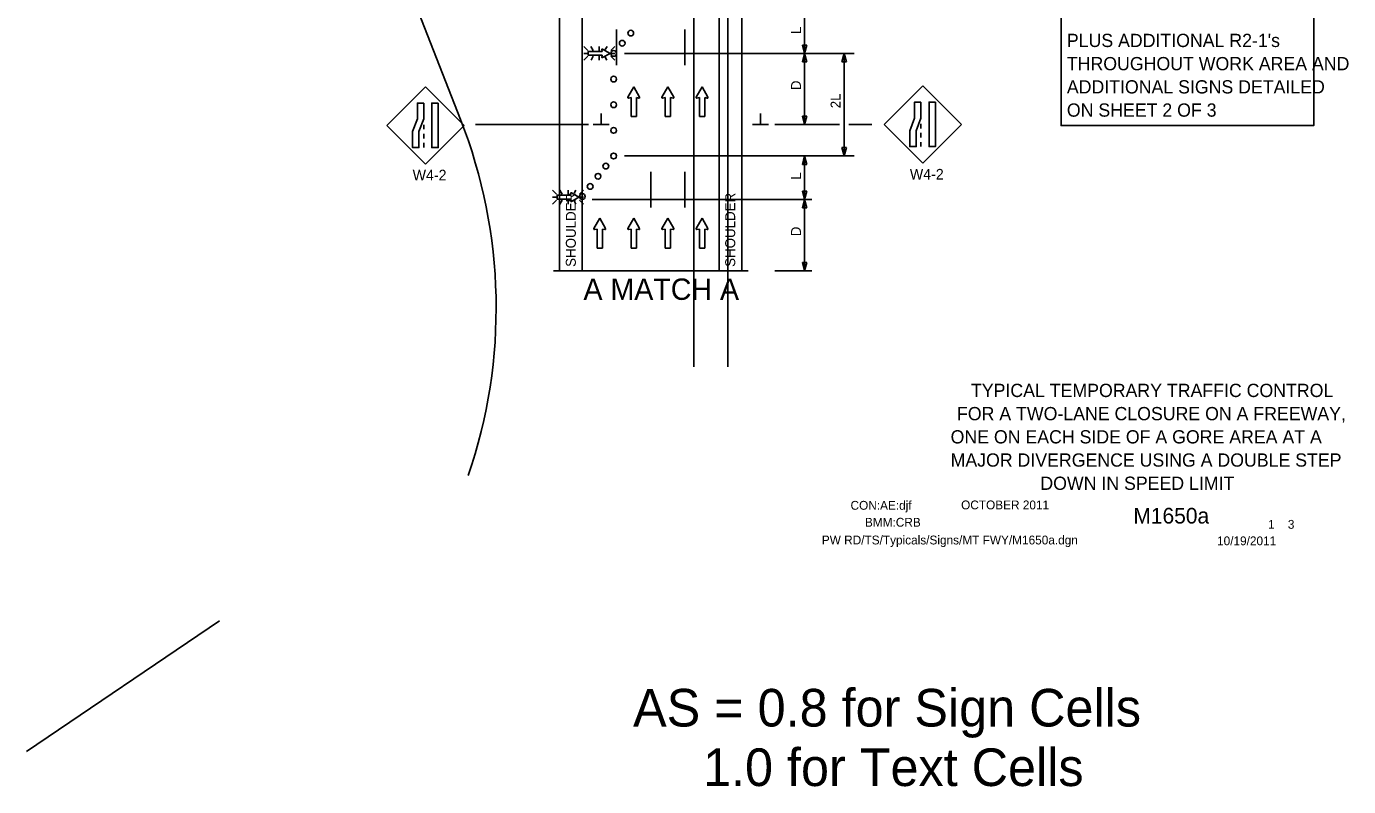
# Model space of a CAD drawing. Extents: x 16512 to 19509, y 5761 to 6974.
# Drawn here: x 16512 to 17440, y 5764 to 6297 of the extents above; entities that cross this region are included whole.
import ezdxf

# ---------------------------------------------------------------- set-up
doc = ezdxf.new("R2010")
doc.units = 0
for name, color, linetype in [('ALI_LEGAL_EX', 7, 'Continuous'), ('BORDER', 7, 'Continuous'), ('BORDER_SIGNAL_WO', 7, 'Continuous'), ('MT_SCRATCH_LEVEL_E', 7, 'Continuous'), ('PAVT_EDGE_EX', 7, 'Continuous'), ('TRAFFIC_SIGNS_PR', 7, 'Continuous'), ('TYPICAL_TEXT_DIMEN_EX', 7, 'Continuous'), ('TYPICAL_TEXT_DIMEN_PR', 7, 'Continuous')]:
    doc.layers.add(name, color=color, linetype=linetype)

msp = doc.modelspace()

# ---------------------------------------------------------------- linework, layer by layer
at = {"layer": 'ALI_LEGAL_EX'}
for p, q in [((16980.68, 6974.12), (16980.68, 6155.98)), ((17004.68, 6974.12), (17004.68, 6155.98)), ((16980.68, 6922.21), (16980.68, 6058.3)), ((17004.68, 6922.21), (17004.68, 6058.3)), ((16594.98, 6800.51), (16817, 6232.14))]:
    msp.add_line(p, q, dxfattribs=at)
for points in [[(16926.45, 6270.33), (16926.45, 6295.33)], [(16974.45, 6270.33), (16974.45, 6295.33)], [(16950.45, 6170.33), (16950.45, 6195.33)], [(16974.45, 6170.33), (16974.45, 6195.33)]]:
    msp.add_lwpolyline(points, dxfattribs=at)
msp.add_arc((16477.95, 6099.7), 364, 341.14594, 21.33672, dxfattribs=at)
at = {"layer": 'BORDER'}
msp.add_line((17289.25, 6011.25), (17289.25, 6011.25), dxfattribs=at)
msp.add_line((17289.25, 6011.25), (17289.25, 6011.25), dxfattribs=at)
at = {"layer": 'MT_SCRATCH_LEVEL_E'}
for p, q in [((16938.54, 6255.03), (16934.43, 6247.79)), ((16942.69, 6247.79), (16938.54, 6255.03)), ((16962.45, 6255.03), (16958.33, 6247.79)), ((16966.59, 6247.79), (16962.45, 6255.03)), ((16986.5, 6255.03), (16982.39, 6247.79)), ((16990.65, 6247.79), (16986.5, 6255.03)), ((16934.91, 6247.11), (16936.69, 6247.43)), ((16936.69, 6247.43), (16936.69, 6234.17)), ((16940.43, 6234.17), (16940.43, 6247.43)), ((16940.43, 6247.43), (16942.21, 6247.11)), ((16958.82, 6247.11), (16960.59, 6247.43)), ((16960.59, 6247.43), (16960.59, 6234.17)), ((16964.34, 6234.17), (16964.34, 6247.43)), ((16964.34, 6247.43), (16966.11, 6247.11)), ((16982.87, 6247.11), (16984.65, 6247.43)), ((16984.65, 6247.43), (16984.65, 6234.17)), ((16988.39, 6234.17), (16988.39, 6247.43)), ((16988.39, 6247.43), (16990.17, 6247.11)), ((16936.69, 6234.17), (16940.43, 6234.17)), ((16960.59, 6234.17), (16964.34, 6234.17)), ((16984.65, 6234.17), (16988.39, 6234.17)), ((16914.64, 6162.72), (16910.53, 6155.48)), ((16918.78, 6155.48), (16914.64, 6162.72)), ((16938.54, 6162.72), (16934.43, 6155.48)), ((16942.69, 6155.48), (16938.54, 6162.72)), ((16962.45, 6162.72), (16958.33, 6155.48)), ((16966.59, 6155.48), (16962.45, 6162.72)), ((16986.5, 6162.72), (16982.39, 6155.48)), ((16990.65, 6155.48), (16986.5, 6162.72)), ((16911.01, 6154.79), (16912.79, 6155.11)), ((16912.79, 6155.11), (16912.79, 6141.85)), ((16916.53, 6141.85), (16916.53, 6155.11)), ((16916.53, 6155.11), (16918.31, 6154.79)), ((16934.91, 6154.79), (16936.69, 6155.11)), ((16936.69, 6155.11), (16936.69, 6141.85)), ((16940.43, 6141.85), (16940.43, 6155.11)), ((16940.43, 6155.11), (16942.21, 6154.79)), ((16958.82, 6154.79), (16960.59, 6155.11)), ((16960.59, 6155.11), (16960.59, 6141.85)), ((16964.34, 6141.85), (16964.34, 6155.11)), ((16964.34, 6155.11), (16966.11, 6154.79)), ((16982.87, 6154.79), (16984.65, 6155.11)), ((16984.65, 6155.11), (16984.65, 6141.85)), ((16988.39, 6141.85), (16988.39, 6155.11)), ((16988.39, 6155.11), (16990.17, 6154.79)), ((16912.79, 6141.85), (16916.53, 6141.85)), ((16936.69, 6141.85), (16940.43, 6141.85)), ((16960.59, 6141.85), (16964.34, 6141.85)), ((16984.65, 6141.85), (16988.39, 6141.85))]:
    msp.add_line(p, q, dxfattribs=at)
for centre, start, end in [((16934.84, 6247.57), 150.42484, 279.96381), ((16942.28, 6247.57), 260.03619, 29.77312), ((16958.74, 6247.57), 150.42484, 279.96381), ((16966.18, 6247.57), 260.03619, 29.77312), ((16982.8, 6247.57), 150.42484, 279.96381), ((16990.24, 6247.57), 260.03619, 29.77312), ((16910.93, 6155.25), 150.42484, 279.96381), ((16918.38, 6155.25), 260.03619, 29.77312), ((16934.84, 6155.25), 150.42484, 279.96381), ((16942.28, 6155.25), 260.03619, 29.77312), ((16958.74, 6155.25), 150.42484, 279.96381), ((16966.18, 6155.25), 260.03619, 29.77312), ((16982.8, 6155.25), 150.42484, 279.96381), ((16990.24, 6155.25), 260.03619, 29.77312)]:
    msp.add_arc(centre, 0.463, start, end, dxfattribs=at)
at = {"layer": 'PAVT_EDGE_EX'}
for p, q in [((16886.45, 6480.53), (16886.45, 6125.9)), ((16902.45, 6480.53), (16902.45, 6125.9)), ((16998.45, 6480.53), (16998.45, 6125.9)), ((17014.45, 6480.53), (17014.45, 6125.9))]:
    msp.add_line(p, q, dxfattribs=at)
at = {"layer": 'TRAFFIC_SIGNS_PR'}
for p, q in [((16906.22, 6280.57), (16903.4, 6283.39)), ((16908.52, 6283.39), (16910.15, 6280.57)), ((16914.31, 6280.57), (16914.31, 6283.39)), ((16919.78, 6283.39), (16918.57, 6281.3)), ((16925.21, 6283.39), (16922.39, 6280.57)), ((16906.22, 6278.54), (16903.4, 6278.54)), ((16906.22, 6276.51), (16903.4, 6273.69)), ((16910.17, 6276.51), (16908.54, 6273.69)), ((16914.31, 6276.51), (16914.31, 6273.69)), ((16918.49, 6275.87), (16919.75, 6273.69)), ((16922.39, 6278.54), (16925.21, 6278.54)), ((16925.21, 6273.69), (16922.39, 6276.51)), ((16792.4, 6255.09), (16765.25, 6227.93)), ((16819.55, 6227.93), (16792.4, 6255.09)), ((17141.36, 6255.7), (17114.21, 6228.54)), ((17168.51, 6228.54), (17141.36, 6255.7)), ((16765.25, 6227.93), (16792.4, 6200.78)), ((16791.15, 6228.43), (16791.15, 6225.23)), ((16792.4, 6200.78), (16819.55, 6227.93)), ((17114.21, 6228.54), (17141.36, 6201.39)), ((17140.11, 6229.03), (17140.11, 6225.83)), ((17141.36, 6201.39), (17168.51, 6228.54)), ((16791.15, 6222.03), (16791.15, 6218.83)), ((17140.11, 6222.63), (17140.11, 6219.43)), ((16791.15, 6215.63), (16791.15, 6212.43)), ((17140.11, 6216.23), (17140.11, 6213.03)), ((16884.35, 6179.62), (16881.53, 6182.44)), ((16886.65, 6182.44), (16888.27, 6179.62)), ((16892.43, 6179.62), (16892.43, 6182.44)), ((16897.9, 6182.44), (16896.69, 6180.35)), ((16903.34, 6182.44), (16900.52, 6179.62)), ((16884.35, 6177.59), (16881.53, 6177.59)), ((16884.35, 6175.56), (16881.53, 6172.74)), ((16888.3, 6175.56), (16886.67, 6172.74)), ((16892.43, 6175.56), (16892.43, 6172.74)), ((16896.62, 6174.92), (16897.88, 6172.74)), ((16900.52, 6177.59), (16903.34, 6177.59)), ((16903.34, 6172.74), (16900.52, 6175.56))]:
    msp.add_line(p, q, dxfattribs=at)
for points in [[(16916.13, 6281.22), (16916.36, 6279.93), (16906.64, 6279.93), (16906.64, 6277.18), (16916.36, 6277.18), (16916.13, 6275.88)], [(16916.63, 6275.53), (16921.94, 6278.54), (16916.63, 6281.58)], [(16894.26, 6180.27), (16894.49, 6178.97), (16884.77, 6178.97), (16884.77, 6176.23), (16894.49, 6176.23), (16894.26, 6174.93)], [(16894.76, 6174.57), (16900.07, 6177.59), (16894.76, 6180.63)]]:
    msp.add_lwpolyline(points, dxfattribs=at)
for points in [[(16791.15, 6243.67), (16791.15, 6232.49), (16787.81, 6223.61), (16787.81, 6212.43), (16783.32, 6212.43), (16783.32, 6223.61), (16786.66, 6232.49), (16786.66, 6243.67)], [(16801.29, 6243.67), (16801.29, 6212.43), (16796.8, 6212.43), (16796.8, 6243.67)], [(17140.11, 6244.28), (17140.11, 6233.1), (17136.77, 6224.22), (17136.77, 6213.03), (17132.27, 6213.03), (17132.27, 6224.22), (17135.62, 6233.1), (17135.62, 6244.28)], [(17150.25, 6244.28), (17150.25, 6213.03), (17145.76, 6213.03), (17145.76, 6244.28)]]:
    msp.add_lwpolyline(points, close=True, dxfattribs=at)
for centre in [(16936.44, 6292.75), (16930.44, 6285.61), (16924.44, 6278.47), (16924.44, 6260.47), (16924.44, 6242.47), (16924.44, 6224.47), (16924.44, 6206.47), (16918.95, 6199.34), (16913.45, 6192.21), (16902.46, 6177.96), (16907.95, 6185.08)]:
    msp.add_circle(centre, 2, dxfattribs=at)
for centre, start, end in [((16916.47, 6281.28), 61.48329, 189.95933), ((16916.47, 6275.82), 170.73078, 298.89165), ((16894.6, 6180.33), 61.48329, 189.95933), ((16894.6, 6174.87), 170.73078, 298.89165)]:
    msp.add_arc(centre, 0.341, start, end, dxfattribs=at)
at = {"layer": 'TYPICAL_TEXT_DIMEN_EX'}
msp.add_lwpolyline([(17238.46, 6313.09), (17415.73, 6313.09), (17415.73, 6227.77), (17238.46, 6227.77)], close=True, dxfattribs=at)
at = {"layer": 'TYPICAL_TEXT_DIMEN_PR'}
for p, q in [((17058.45, 6278.47), (17058.45, 6307.03)), ((17058.45, 6278.47), (17056.88, 6284.33)), ((17056.88, 6284.33), (17058.45, 6284.33)), ((17058.45, 6284.33), (17060.02, 6284.33)), ((17060.02, 6284.33), (17058.45, 6278.47)), ((17093.24, 6278.47), (16931.95, 6278.47)), ((17056.88, 6272.61), (17058.45, 6278.47)), ((17058.45, 6272.61), (17056.88, 6272.61)), ((17058.45, 6278.47), (17058.45, 6228.47)), ((17058.45, 6278.47), (17060.02, 6272.61)), ((17060.02, 6272.61), (17058.45, 6272.61)), ((17084.68, 6272.61), (17086.25, 6278.47)), ((17086.25, 6272.61), (17084.68, 6272.61)), ((17086.25, 6278.47), (17087.82, 6272.61)), ((17086.25, 6278.47), (17086.25, 6206.47)), ((17087.82, 6272.61), (17086.25, 6272.61)), ((16915.73, 6228.47), (16915.73, 6236.25)), ((17027.57, 6228.47), (17027.57, 6236.25)), ((16827.54, 6228.47), (16906.74, 6228.47)), ((16921.36, 6228.47), (16910.11, 6228.47)), ((17033.2, 6228.47), (17021.95, 6228.47)), ((17082.83, 6228.47), (17037.45, 6228.47)), ((17058.45, 6228.47), (17056.88, 6234.33)), ((17056.88, 6234.33), (17058.45, 6234.33)), ((17058.45, 6234.33), (17060.02, 6234.33)), ((17060.02, 6234.33), (17058.45, 6228.47)), ((17105.6, 6228.47), (17089.54, 6228.47)), ((17086.25, 6206.47), (17084.68, 6212.33)), ((17084.68, 6212.33), (17086.25, 6212.33)), ((17086.25, 6212.33), (17087.82, 6212.33)), ((17087.82, 6212.33), (17086.25, 6206.47)), ((16931.95, 6206.47), (17093.24, 6206.47)), ((17056.88, 6200.61), (17058.45, 6206.47)), ((17058.45, 6200.61), (17056.88, 6200.61)), ((17058.45, 6175.9), (17058.45, 6206.47)), ((17058.45, 6206.47), (17060.02, 6200.61)), ((17060.02, 6200.61), (17058.45, 6200.61)), ((17058.45, 6175.9), (17056.88, 6181.77)), ((17056.88, 6181.77), (17058.45, 6181.77)), ((17058.45, 6181.77), (17060.02, 6181.77)), ((17060.02, 6181.77), (17058.45, 6175.9)), ((16909.4, 6175.9), (17063.45, 6175.9)), ((17056.88, 6170.04), (17058.45, 6175.9)), ((17058.45, 6175.9), (17058.45, 6125.9)), ((17058.45, 6175.9), (17060.02, 6170.04)), ((17058.45, 6170.04), (17056.88, 6170.04)), ((17060.02, 6170.04), (17058.45, 6170.04)), ((16882.15, 6125.9), (17018.8, 6125.9)), ((17063.45, 6125.9), (17037.45, 6125.9)), ((17058.45, 6125.9), (17056.88, 6131.77)), ((17056.88, 6131.77), (17058.45, 6131.77)), ((17058.45, 6131.77), (17060.02, 6131.77)), ((17060.02, 6131.77), (17058.45, 6125.9)), ((16647.75, 5880), (16512.32, 5788.38))]:
    msp.add_line(p, q, dxfattribs=at)

# ---------------------------------------------------------------- texts
at = {"layer": 'BORDER'}
for s, p in [('TYPICAL TEMPORARY TRAFFIC CONTROL', (17175.21, 6037.21)), ('FOR A TWO-LANE CLOSURE ON A FREEWAY,', (17165.41, 6020.91)), ('ONE ON EACH SIDE OF A GORE AREA AT A ', (17160.92, 6004.62)), ('MAJOR DIVERGENCE USING A DOUBLE STEP ', (17160.92, 5988.32)), ('DOWN IN SPEED LIMIT', (17223.92, 5972.02))]:
    msp.add_text(s, height=9.3, dxfattribs=at).set_placement(p)
at = {"layer": 'BORDER_SIGNAL_WO'}
for s, height, p in [('CON:AE:djf  ', 6.2, (17090.69, 5958.06)), ('    OCTOBER 2011    ', 6.2, (17159.08, 5958.34)), ('    M1650a   ', 11, (17272.86, 5948.38)), ('BMM:CRB   ', 6.2, (17100.81, 5946.17)), (' 1    3 ', 6.2, (17381.45, 5944.7)), ('PW RD/TS/Typicals/Signs/MT FWY/M1650a.dgn      ', 6.2, (17070.55, 5933.71)), ('10/19/2011    ', 6.2, (17347.93, 5933.13)), ('AS = 0.8 for Sign Cells', 26.4241, (16938.08, 5805.84)), ('     1.0 for Text Cells', 26.4241, (16938.08, 5764.05))]:
    msp.add_text(s, height=height, dxfattribs=at).set_placement(p)
at = {"layer": 'TRAFFIC_SIGNS_PR'}
for p in [(16783.36, 6189.34), (17132.32, 6189.95)]:
    msp.add_text('W4-2', height=7.44, dxfattribs=at).set_placement(p)
at = {"layer": 'TYPICAL_TEXT_DIMEN_EX'}
for s, p in [("PLUS ADDITIONAL R2-1's", (17242.51, 6282.97)), ('THROUGHOUT WORK AREA AND', (17242.51, 6266.67)), ('ADDITIONAL SIGNS DETAILED', (17242.51, 6250.37)), ('ON SHEET 2 OF 3', (17242.51, 6234.07))]:
    msp.add_text(s, height=9.3, dxfattribs=at).set_placement(p)
at = {"layer": 'TYPICAL_TEXT_DIMEN_PR'}
for s, p in [('L', (17055.98, 6292.11)), ('D', (17055.89, 6252.69)), ('2L', (17083.69, 6239.97)), ('L', (17055.89, 6189.76)), ('SHOULDER', (16897.88, 6128.61)), ('SHOULDER', (17009.74, 6128.61)), ('D', (17055.89, 6150.12))]:
    msp.add_text(s, height=7, rotation=90, dxfattribs=at).set_placement(p)
msp.add_text('A MATCH A', height=15, dxfattribs=at).set_placement((16903.24, 6105.44))

doc.saveas('drawing.dxf')
